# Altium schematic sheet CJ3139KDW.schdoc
size 127 x 101 mm
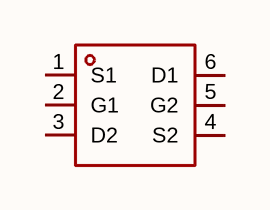
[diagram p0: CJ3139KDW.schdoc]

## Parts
Q?  cj3139kdw  [SOT-363_L2.0-W1.3-P0.65-LS2.1-BR]  (value not drawn)

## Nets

Not connected (* = marked no-connect by the designer): Q? 1(S1) 2(G1) 3(D2) 4(S2) 5(G2) 6(D1)

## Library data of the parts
Q? = cj3139kdw: 数量:2个P沟道;漏源电压(Vdss):20V;连续漏极电流(Id):660mA;导通电阻(RDS(on)):520mΩ@4.5V;耗散功率(Pd):150mW;阈值电压(Vgs(th)):1.1V;; Manufacturer: CJ(江苏长电/长晶); AddInBom: yes; ModelId: ea15c7b026c54341854a7f0d9614aed9; ModelName: SOT-363-6P_L2.0-W1.3-H1.1-LS2.0-P0.65; ModelTransform: 83.17133,78.74,0,180,0,0,0,0,0; Number: 2个P沟道; Drain to Source Voltage: 20V; Current - Continuous Drain(Id): 660mA; Pd - Power Dissipation: 150mW; Gate Threshold Voltage (Vgs(th)): 1.1V; Input Capacitance(Ciss): 170pF; Reverse Transfer Capacitance (Crss@Vds): 15pF; Type: P沟道; Output Capacitance(Coss): 25pF; Vgs: ±12V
